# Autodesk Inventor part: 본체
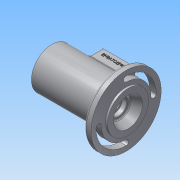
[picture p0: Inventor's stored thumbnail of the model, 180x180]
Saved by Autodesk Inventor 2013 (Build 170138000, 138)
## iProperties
Created: 2017-05
Part Number: 본체
Material: 알루미늄 6061
Document SubType Name: Modeling
Designer: Administrator
Density: 2.71 g/cm^3
Mass: 679.727 g
Surface Area: 615.711 cm^2
Volume: 250.822 cm^3
Author: Administrator
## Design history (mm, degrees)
sketch "스케치1"
  geometry: L1 (-56, 0)-(-56, 21); L2 (-56, 31)-(46, 31); L3 (46, 31)-(46, 53); L4 (46, 53)-(56, 53); L5 (56, 53)-(56, 31); L6 (56, 31)-(59, 31); L7 (59, 31)-(59, 22); L8 (59, 0)-(-56, 0); L9 (-47, 21)-(-47, 24); L10 (-47, 24)-(-44, 24); L11 (-44, 24)-(-44, 20); L12 (-44, 20)-(-35, 20); L13 (-35, 20)-(-35, 17.5); L14 (-35, 17.5)-(-31.75, 17.5); L15 (-31.75, 17.5)-(-31.75, 18.5); L16 (-31.75, 18.5)-(-30, 18.5); L17 (-30, 18.5)-(-30, 17.5); L18 (-30, 17.5)-(-19, 17.5); L19 (-19, 17.5)-(-19, 26); L20 (-19, 26)-(19, 26); L21 (19, 26)-(19, 17.5); L22 (19, 17.5)-(30, 17.5); L23 (35, 10)-(37.7, 10); L24 (37.7, 10)-(37.7, 12.5); L25 (37.7, 12.5)-(45, 12.5); L26 (45, 12.5)-(45, 16); L27 (45, 16)-(59, 22); L28 (30, 16.5)-(30, 17.5); L29 (-47, 21)-(-56, 21); L30 (30, 16.5)-(35, 16.5); L31 (35, 16.5)-(35, 10); L32 (-56, 21)-(-56, 31); L33 (59, 22)-(59, 0); 1 further point
  constraints: 66 end point, 16 parallel, 7 perpendicular, 4 collinear, 3 horizontal, 3 vertical, 1 horizontal alignment
  dimensions: "d0" = 62 diameter of L6 L8; "d2" = 106 diameter of L4 L8; "d4" = 115 distance of L8.start L1.start; "d5" = 3 distance of L5.end L6.end; "d7" = 56 distance from line of point (0, 0) L1; "d8" = 25 diameter of L25 L8; "d9" = 20 diameter of L23 L8; "d11" = 32 diameter of L26.end L8; "d12" = 44 diameter of L7.end L8; "d14" = 14 horizontal distance of L26.end L7.end; "d19" = 38 distance of L19.end L20.end; "d20" = 52 diameter of L20 L8; "d21" = 11 distance of L17.end L18.end; "d22" = 1.75 distance of L15.end L16.end; "d23" = 37 diameter of L16 L8; "d24" = 35 diameter of L18 L8; "d25" = 3 distance of L9.end L10.end; "d26" = 12 distance between parallel lines of L1 L11; "d27" = 48 diameter of L10 L8; "d28" = 42 diameter of L29 L8; "d29" = 40 diameter of L12 L8; "d30" = 21 distance between parallel lines of L1 L13; "d35" = 11 distance of L21.end L22.end; "d36" = 33 diameter of L30 L8; "d37" = 5 distance of L28.start L30.end; "d38" = 2.7 distance of L23.start L23.end; "d40" = 26 distance from line of L1 L17.end; "d101" = 13 distance between parallel lines of L7 L3
revolve "회전1" sketch "스케치1" stored, may be unused: angle "d41" = 90 deg
feature "스레드1" dims "d42" = 10, "d43" = 0
node "작업 평면1"
sketch "스케치2"
  geometry: L1 (-25, 20)-(25, 20); L2 (25, 20)-(25, -20); L3 (25, -20)-(-25, -20); L4 (-25, -20)-(-25, 20); L5 (-16, 11)-(16, 11); L6 (16, 11)-(16, -11); L7 (16, -11)-(-16, -11); L8 (-16, -11)-(-16, 11); 5 further points
  constraints: 16 end point, 4 midpoint, 4 parallel, 2 horizontal, 2 horizontal alignment, 2 perpendicular, 2 vertical alignment
  dimensions: "d45" = 50 distance of L2.end L3.end; "d47" = 40 distance of L1.end L2.end; "d59" = 22 distance of L5.end L6.end; "d60" = 32 distance of L5.start L5.end
extrude "돌출1" join sketch "스케치2" stored distance "d48" = 10; taper "d49" = 0 deg
sketch "스케치3"
  geometry: A1 r 41.5 centre (0, 0) between (0, 41.5) and (-41.5, 0); A2 r 4 centre (0, 41.5) between (0, 45.5) and (0, 37.5); A3 r 4 centre (-41.5, 0) between (-37.5, 0) and (-45.5, 0); A4 r 4 centre (41.5, 0) between (37.5, 0) and (45.5, 0); A5 r 4 centre (0, -41.5) between (0, -45.5) and (0, -37.5); A6 r 37.5 centre (0, 0) between (37.5, 0) and (0, 37.5); A7 r 37.5 centre (0, 0) between (-37.5, 0) and (0, -37.5); A8 r 45.5 centre (0, 0) between (45.5, 0) and (0, 45.5); A9 r 45.5 centre (0, 0) between (-45.5, 0) and (0, -45.5); 1 further point
  constraints: 20 point on circle, 9 centre point, 5 tangent, 3 coincident, 2 horizontal alignment, 2 vertical alignment
  dimensions: "d91" = 83 diameter of A1; "d94" = 8 diameter of A4; "d95" = 4 radius of A5; "d96" = 4 radius of A2
extrude "돌출2" cut sketch "스케치3" stored distance "d57" = 10; taper "d58" = 0 deg
extrude "돌출3" cut sketch "스케치2" stored distance "d61" = 10; taper "d62" = 0 deg
sketch "스케치5"
  geometry: 2 further points
  dimensions: "d63" = 15.5 vertical distance of point (0, 0) point (-20.5, 15.5); "d64" = 20.5 horizontal distance of point (0, 0) point (-20.5, 15.5)
hole "구멍1" sketch "스케치5" at (-20.5, 15.5) diameter "d65" = 2.459; stored, may be unused: countersink angle "d69" = 90 deg, drill point angle "d71" = 118 deg; dims "d66" = 6, "d67" = 4, "d68" = 2, "d70" = 8
chamfer "모따기1" distance "d78" = 1; stored, may be unused: second distance "d79" = 2, angle "d80" = 45 deg
fillet "모깎기1" dims "d81" = 3
chamfer "모따기2" distance "d82" = 0.7; stored, may be unused: second distance "d83" = 2, angle "d84" = 30 deg
fillet "모깎기2" dims "d85" = 3
fillet "모깎기3" dims "d86" = 0.3
chamfer "모따기3" distance "d87" = 1; stored, may be unused: second distance "d88" = 2, angle "d89" = 30 deg
sketch "스케치10"
  geometry: L1 (44, 0)-(0, 0) reference; L2 (-34, -75)-(-34, -13) reference; 2 further points
  constraints: 1 other
  dimensions: "d97" = 56 distance from line of L2 point (22, -8); "d98" = 8 distance from line of L1 point (22, -8)
feature "엠보싱1" sketch "스케치10" dims "d99" = 0.5, "d100" = 0
node "솔리드1"
pattern_linear "직사각형 패턴1" dims "d74" = 31, "d77" = 41
other parameters: "d44" = 44, "d56" = 91, "d92" = 75, "d93" = 91
